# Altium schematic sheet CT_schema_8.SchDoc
size 274 x 160 mm
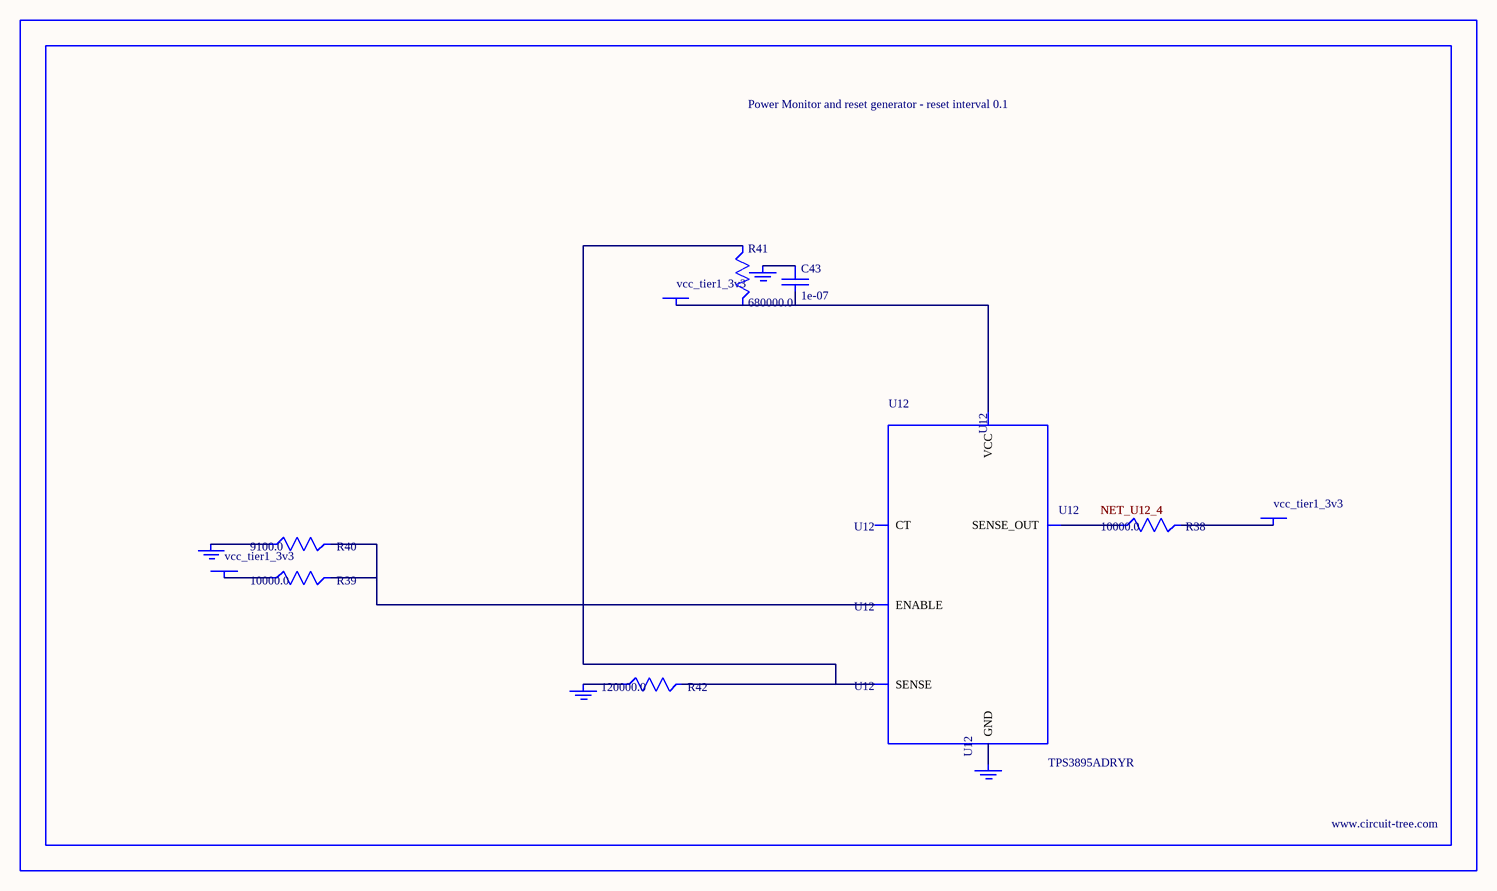
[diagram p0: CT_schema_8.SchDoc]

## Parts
BORDER7  (no value)
C43  1e-07  [C0402]
GND_INSTANCE_7_0  (no value)
GND_INSTANCE_7_1  (no value)
GND_INSTANCE_7_2  (no value)
GND_INSTANCE_7_3  (no value)
POWER_INSTANCE_7_0  vcc_tier1_3v3
POWER_INSTANCE_7_1  vcc_tier1_3v3
POWER_INSTANCE_7_2  vcc_tier1_3v3
R38  10000.0  [R0603]
R39  10000.0  [R0603]
R40  9100.0  [R0603]
R41  680000.0  [R0603]
R42  120000.0  [R0603]
U12  TPS3895ADRYR  [SON-6]

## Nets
NetC43_1: C43.1 GND_INSTANCE_7_2.0(GND)
NetC43_2: C43.2 POWER_INSTANCE_7_2.0(PWR) R41.2 U12.6(VCC)
NetGND_INSTANCE_7_0_0: GND_INSTANCE_7_0.0(GND) R40.1
NetGND_INSTANCE_7_1_0: GND_INSTANCE_7_1.0(GND) R42.1
NetGND_INSTANCE_7_3_0: GND_INSTANCE_7_3.0(GND) U12.2(GND)
NetPOWER_INSTANCE_7_0_0: POWER_INSTANCE_7_0.0(PWR) R39.1
NetPOWER_INSTANCE_7_1_0: POWER_INSTANCE_7_1.0(PWR) R38.2
NetR38_1: R38.1 U12.4(SENSE_OUT)
NetR39_2: R39.2 R40.2 U12.1(ENABLE)
NetR41_1: R41.1 R42.2 U12.3(SENSE)

Not connected (* = marked no-connect by the designer): U12 5(CT)

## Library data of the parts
BORDER7 = BORDER_PAGE7
C43 = C0402C104K3RACTU
GND_INSTANCE_7_0-GND_INSTANCE_7_3 = GND
POWER_INSTANCE_7_0-POWER_INSTANCE_7_2 = PWR
R38 R39 = RC0603JR-0710KL
R40 = RC0603JR-079K1L
R41 = RC0603JR-07680KL
R42 = RC0603JR-07120KL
